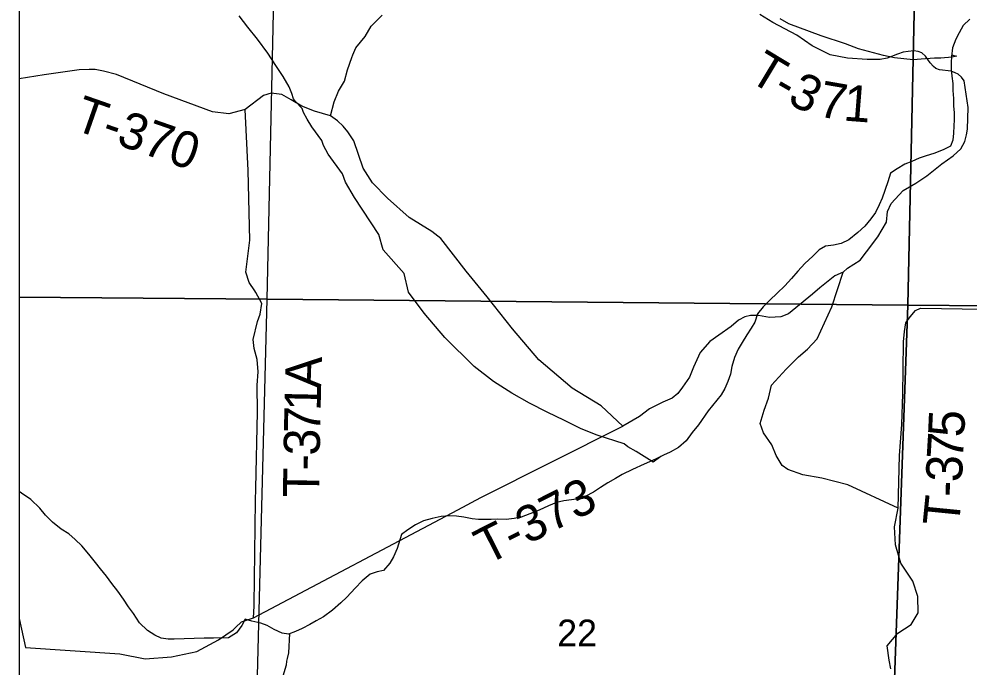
# Model space of a CAD drawing. Extents: x 0 to 34, y 0 to 22.
# Drawn here: x 2.1 to 3.589, y 16.55 to 17.566 of the extents above; entities that cross this region are included whole.
import ezdxf

# ---------------------------------------------------------------- set-up
doc = ezdxf.new("R2010")
doc.units = 0
for name, color, linetype in [('Default', 7, 'Continuous'), ('GM_X_Minor_River', 7, 'Continuous'), ('GM_X_Section', 7, 'Continuous'), ('GM_X_Section_Text', 7, 'Continuous'), ('GM_X_Township_Road', 7, 'Continuous'), ('GM_X_Township_Road_Text', 7, 'Continuous'), ('SH_Cut_Line', 7, 'Continuous'), ('SH_Data', 7, 'Continuous')]:
    doc.layers.add(name, color=color, linetype=linetype)

msp = doc.modelspace()

# ---------------------------------------------------------------- linework, layer by layer
at = {"layer": 'Default'}
for p, q in [((2.1, 19.1502), (2.1, 14.1)), ((2.1, 18.1363), (2.1, 17.1299)), ((2.4891, 17.1265), (2.5107, 18.1291)), ((2.1, 17.1299), (2.4891, 17.1265)), ((2.1, 17.1299), (2.1, 16.1234)), ((2.4891, 17.1265), (2.1, 17.1299)), ((2.4631, 16.1204), (2.4891, 17.1265))]:
    msp.add_line(p, q, dxfattribs=at)
at = {"layer": 'GM_X_Minor_River'}
for p, q in [((2.4586, 17.5536), (2.445, 17.5713)), ((3.3067, 17.5584), (3.293, 17.5666)), ((3.5906, 17.5658), (3.5799, 17.5559)), ((2.474, 17.5344), (2.4586, 17.5536)), ((3.339, 17.5464), (3.3067, 17.5584)), ((3.3573, 17.5395), (3.339, 17.5464)), ((3.5738, 17.5443), (3.5688, 17.5343)), ((3.5799, 17.5559), (3.5738, 17.5443)), ((2.4899, 17.5123), (2.474, 17.5344)), ((3.3957, 17.5272), (3.3573, 17.5395)), ((3.5688, 17.5343), (3.5635, 17.5211)), ((3.4159, 17.5195), (3.3957, 17.5272)), ((3.455, 17.5091), (3.4159, 17.5195)), ((3.5635, 17.5211), (3.5616, 17.5074)), ((2.5027, 17.4931), (2.4899, 17.5123)), ((3.4724, 17.5052), (3.455, 17.5091)), ((3.5016, 17.5019), (3.4724, 17.5052)), ((3.5144, 17.5029), (3.5016, 17.5019)), ((3.5352, 17.5047), (3.5144, 17.5029)), ((3.545, 17.5049), (3.5352, 17.5047)), ((3.5628, 17.5063), (3.545, 17.5049)), ((3.5616, 17.5074), (3.5612, 17.4979)), ((3.562, 17.51), (3.5699, 17.5076)), ((3.5699, 17.5076), (3.5628, 17.5063)), ((2.5143, 17.4761), (2.5027, 17.4931)), ((3.5612, 17.4979), (3.5615, 17.4872)), ((3.5615, 17.4872), (3.5626, 17.4766)), ((2.5233, 17.4599), (2.5143, 17.4761)), ((3.5626, 17.4766), (3.5637, 17.4652)), ((2.5276, 17.4493), (2.5233, 17.4599)), ((3.5637, 17.4652), (3.564, 17.4538)), ((2.5304, 17.441), (2.5276, 17.4493)), ((2.5335, 17.4369), (2.5304, 17.441)), ((3.564, 17.4538), (3.5648, 17.4416)), ((3.5648, 17.4416), (3.5651, 17.4302)), ((2.5439, 17.4256), (2.5335, 17.4369)), ((2.5459, 17.4196), (2.5439, 17.4256)), ((3.5651, 17.4302), (3.5659, 17.4192)), ((2.5518, 17.409), (2.5459, 17.4196)), ((3.5659, 17.4192), (3.5662, 17.4082)), ((2.5592, 17.3969), (2.5518, 17.409)), ((2.5746, 17.3755), (2.5592, 17.3969)), ((3.5657, 17.3986), (3.5649, 17.3872)), ((3.5662, 17.4082), (3.5657, 17.3986)), ((3.5649, 17.3872), (3.5641, 17.3761)), ((2.5771, 17.3675), (2.5746, 17.3755)), ((2.5848, 17.354), (2.5771, 17.3675)), ((3.5603, 17.3665), (3.5486, 17.3608)), ((3.5641, 17.3761), (3.5603, 17.3665)), ((2.6069, 17.3235), (2.5848, 17.354)), ((3.5223, 17.3516), (3.511, 17.3478)), ((3.5344, 17.3554), (3.5223, 17.3516)), ((3.5486, 17.3608), (3.5344, 17.3554)), ((3.4889, 17.3384), (3.4766, 17.3311)), ((3.4998, 17.3425), (3.4889, 17.3384)), ((3.511, 17.3478), (3.4998, 17.3425)), ((2.6117, 17.3103), (2.6069, 17.3235)), ((3.4661, 17.3243), (3.462, 17.3109)), ((3.4766, 17.3311), (3.4661, 17.3243)), ((2.6257, 17.2861), (2.6117, 17.3103)), ((3.462, 17.3109), (3.4529, 17.2851)), ((2.6641, 17.2282), (2.6257, 17.2861)), ((3.4529, 17.2851), (3.4486, 17.2747)), ((3.4426, 17.2627), (3.4356, 17.2526)), ((3.4486, 17.2747), (3.4426, 17.2627)), ((3.4356, 17.2526), (3.4261, 17.2412)), ((3.415, 17.231), (3.4009, 17.2199)), ((3.4261, 17.2412), (3.415, 17.231)), ((2.6709, 17.2043), (2.6641, 17.2282)), ((3.4009, 17.2199), (3.3889, 17.2142)), ((2.7037, 17.1668), (2.6709, 17.2043)), ((3.3546, 17.204), (3.3443, 17.1941)), ((3.3643, 17.2096), (3.3546, 17.204)), ((3.3768, 17.2115), (3.3643, 17.2096)), ((3.3889, 17.2142), (3.3768, 17.2115)), ((3.3443, 17.1941), (3.3317, 17.1827)), ((3.3317, 17.1827), (3.3211, 17.1706)), ((2.7106, 17.1376), (2.7037, 17.1668)), ((3.3112, 17.1592), (3.3005, 17.1474)), ((3.3211, 17.1706), (3.3112, 17.1592)), ((3.3005, 17.1474), (3.2887, 17.136)), ((2.735, 17.1049), (2.7106, 17.1376)), ((3.2887, 17.136), (3.2768, 17.125)), ((3.2665, 17.1144), (3.2577, 17.1035)), ((3.2768, 17.125), (3.2665, 17.1144)), ((2.7678, 17.0666), (2.735, 17.1049)), ((3.2577, 17.1035), (3.2536, 17.0908)), ((3.2536, 17.0908), (3.2478, 17.0811)), ((3.2409, 17.0706), (3.2336, 17.0589)), ((3.2478, 17.0811), (3.2409, 17.0706)), ((2.8136, 17.0209), (2.7678, 17.0666)), ((3.2336, 17.0589), (3.2275, 17.0481)), ((3.2275, 17.0481), (3.2214, 17.0353)), ((3.2214, 17.0353), (3.2177, 17.0211)), ((2.8438, 16.9975), (2.8136, 17.0209)), ((3.2154, 17.0092), (3.2112, 16.9977)), ((3.2177, 17.0211), (3.2154, 17.0092)), ((2.8725, 16.9793), (2.8438, 16.9975)), ((3.2112, 16.9977), (3.2066, 16.9865)), ((2.9004, 16.9634), (2.8725, 16.9793)), ((3.2066, 16.9865), (3.2008, 16.9764)), ((2.9278, 16.9494), (2.9004, 16.9634)), ((3.2008, 16.9764), (3.1803, 16.9514)), ((2.9553, 16.9361), (2.9278, 16.9494)), ((3.1803, 16.9514), (3.165, 16.9296)), ((2.9812, 16.9232), (2.9553, 16.9361)), ((3.0063, 16.9134), (2.9812, 16.9232)), ((3.165, 16.9296), (3.1555, 16.9175)), ((3.0485, 16.9), (3.0063, 16.9134)), ((3.146, 16.9047), (3.1338, 16.894)), ((3.1555, 16.9175), (3.146, 16.9047)), ((3.0543, 16.8951), (3.0485, 16.9)), ((3.0676, 16.8878), (3.0543, 16.8951)), ((3.1338, 16.894), (3.1207, 16.8867)), ((3.0886, 16.8748), (3.0676, 16.8878)), ((3.0978, 16.8757), (3.0802, 16.868)), ((3.0944, 16.8711), (3.0886, 16.8748)), ((3.1062, 16.8798), (3.0944, 16.8711)), ((3.1106, 16.8819), (3.0978, 16.8757)), ((3.1207, 16.8867), (3.1106, 16.8819)), ((3.0615, 16.8594), (3.0457, 16.8516)), ((3.0802, 16.868), (3.0615, 16.8594)), ((3.0353, 16.8452), (3.0229, 16.8387)), ((3.0457, 16.8516), (3.0353, 16.8452)), ((3.0117, 16.8315), (3.0006, 16.824)), ((3.0229, 16.8387), (3.0117, 16.8315)), ((2.1041, 16.8224), (2.1, 16.8249)), ((2.1185, 16.8122), (2.1041, 16.8224)), ((2.9875, 16.8171), (2.9777, 16.8137)), ((3.0006, 16.824), (2.9875, 16.8171)), ((2.1326, 16.799), (2.1185, 16.8122)), ((2.9301, 16.8023), (2.9155, 16.7958)), ((2.9425, 16.8077), (2.9301, 16.8023)), ((2.9542, 16.8103), (2.9425, 16.8077)), ((2.9663, 16.8118), (2.9542, 16.8103)), ((2.9777, 16.8137), (2.9663, 16.8118)), ((2.1413, 16.7878), (2.1326, 16.799)), ((2.1527, 16.7767), (2.1413, 16.7878)), ((2.7618, 16.7856), (2.7475, 16.7825)), ((2.7747, 16.7868), (2.7618, 16.7856)), ((2.7858, 16.7864), (2.7747, 16.7868)), ((2.7972, 16.7848), (2.7858, 16.7864)), ((2.8106, 16.7822), (2.7972, 16.7848)), ((2.887, 16.7846), (2.8764, 16.7824)), ((2.9009, 16.79), (2.887, 16.7846)), ((2.9155, 16.7958), (2.9009, 16.79)), ((2.1663, 16.7658), (2.1527, 16.7767)), ((2.7216, 16.7729), (2.7093, 16.7649)), ((2.7343, 16.7791), (2.7216, 16.7729)), ((2.7475, 16.7825), (2.7343, 16.7791)), ((2.8205, 16.781), (2.8106, 16.7822)), ((2.83, 16.7813), (2.8205, 16.781)), ((2.8403, 16.7812), (2.83, 16.7813)), ((2.8506, 16.7816), (2.8403, 16.7812)), ((2.8639, 16.7812), (2.8506, 16.7816)), ((2.8764, 16.7824), (2.8639, 16.7812)), ((2.1783, 16.7585), (2.1663, 16.7658)), ((2.1881, 16.7497), (2.1783, 16.7585)), ((2.6996, 16.7574), (2.693, 16.7355)), ((2.7093, 16.7649), (2.6996, 16.7574)), ((2.1983, 16.7397), (2.1881, 16.7497)), ((2.2093, 16.7267), (2.1983, 16.7397)), ((2.22, 16.7138), (2.2093, 16.7267)), ((2.693, 16.7355), (2.687, 16.7227)), ((2.2279, 16.7037), (2.22, 16.7138)), ((2.6812, 16.7123), (2.6713, 16.7013)), ((2.687, 16.7227), (2.6812, 16.7123)), ((2.237, 16.6922), (2.2279, 16.7037)), ((2.6506, 16.6953), (2.638, 16.6847)), ((2.6615, 16.6991), (2.6506, 16.6953)), ((2.6713, 16.7013), (2.6615, 16.6991)), ((2.2457, 16.6807), (2.237, 16.6922)), ((2.2548, 16.6684), (2.2457, 16.6807)), ((2.638, 16.6847), (2.6269, 16.6736)), ((2.2636, 16.6561), (2.2548, 16.6684)), ((2.6269, 16.6736), (2.614, 16.6592)), ((2.2715, 16.6442), (2.2636, 16.6561)), ((2.6044, 16.6505), (2.5915, 16.6386)), ((2.614, 16.6592), (2.6044, 16.6505)), ((2.2795, 16.6334), (2.2715, 16.6442)), ((2.5915, 16.6386), (2.5773, 16.6283)), ((2.2891, 16.6188), (2.2795, 16.6334)), ((2.4543, 16.6248), (2.4492, 16.6148)), ((2.465, 16.6217), (2.4543, 16.6248)), ((2.4792, 16.6184), (2.465, 16.6217)), ((2.5661, 16.6219), (2.556, 16.6166)), ((2.5773, 16.6283), (2.5661, 16.6219)), ((2.3012, 16.6067), (2.2891, 16.6188)), ((2.3128, 16.5994), (2.3012, 16.6067)), ((2.4492, 16.6148), (2.4409, 16.6031)), ((2.4888, 16.6149), (2.4792, 16.6184)), ((2.5, 16.6084), (2.4888, 16.6149)), ((2.5123, 16.603), (2.5, 16.6084)), ((2.5332, 16.6056), (2.5223, 16.6014)), ((2.5441, 16.6101), (2.5332, 16.6056)), ((2.556, 16.6166), (2.5441, 16.6101)), ((2.3229, 16.5948), (2.3128, 16.5994)), ((2.3339, 16.5936), (2.3229, 16.5948)), ((2.3434, 16.5935), (2.3339, 16.5936)), ((2.3902, 16.595), (2.3434, 16.5935)), ((2.405, 16.5947), (2.3902, 16.595)), ((2.4282, 16.5954), (2.405, 16.5947)), ((2.4409, 16.6031), (2.4282, 16.5954)), ((2.5223, 16.6014), (2.5123, 16.603)), ((2.5239, 16.6021), (2.5223, 16.572)), ((2.5202, 16.5628), (2.5191, 16.5586)), ((2.5223, 16.572), (2.5202, 16.5628)), ((2.5188, 16.5525), (2.5134, 16.5353)), ((2.5191, 16.5586), (2.5188, 16.5525))]:
    msp.add_line(p, q, dxfattribs=at)
at = {"layer": 'GM_X_Section'}
for p, q in [((2.4891, 17.1265), (2.5107, 18.1291)), ((3.5154, 18.1224), (3.4934, 17.1171)), ((3.4934, 17.1171), (3.5154, 18.1224)), ((2.4631, 16.1204), (2.4891, 17.1265)), ((3.4934, 17.1171), (2.4891, 17.1265)), ((2.4891, 17.1265), (3.4934, 17.1171)), ((3.4934, 17.1171), (3.4577, 16.1051)), ((3.4577, 16.1051), (3.4934, 17.1171)), ((4.4928, 17.1099), (3.4934, 17.1171)), ((3.4934, 17.1171), (4.4928, 17.1099))]:
    msp.add_line(p, q, dxfattribs=at)
at = {"layer": 'GM_X_Township_Road'}
for p, q in [((2.6521, 17.5547), (2.6693, 17.5724)), ((3.2818, 17.5607), (3.2613, 17.5733)), ((3.3192, 17.5406), (3.2818, 17.5607)), ((2.6426, 17.5387), (2.6521, 17.5547)), ((2.6278, 17.521), (2.6426, 17.5387)), ((3.3432, 17.5241), (3.3192, 17.5406)), ((2.6233, 17.5099), (2.6278, 17.521)), ((3.3715, 17.5102), (3.3432, 17.5241)), ((3.4861, 17.5139), (3.4771, 17.5108)), ((3.494, 17.5153), (3.4861, 17.5139)), ((3.5026, 17.5161), (3.494, 17.5153)), ((3.5097, 17.5154), (3.5026, 17.5161)), ((3.5153, 17.5131), (3.5097, 17.5154)), ((2.615, 17.4862), (2.6217, 17.5059)), ((2.6217, 17.5059), (2.6233, 17.5099)), ((3.3989, 17.5049), (3.3715, 17.5102)), ((3.4297, 17.5025), (3.3989, 17.5049)), ((3.4498, 17.5025), (3.4297, 17.5025)), ((3.461, 17.5045), (3.4498, 17.5025)), ((3.4771, 17.5108), (3.461, 17.5045)), ((3.5213, 17.5079), (3.5153, 17.5131)), ((3.5282, 17.4974), (3.5213, 17.5079)), ((2.1944, 17.4865), (2.1394, 17.4785)), ((2.2101, 17.487), (2.1944, 17.4865)), ((2.2193, 17.4867), (2.2101, 17.487)), ((2.2326, 17.4843), (2.2193, 17.4867)), ((2.2526, 17.479), (2.2326, 17.4843)), ((2.6105, 17.4685), (2.615, 17.4862)), ((3.5335, 17.4919), (3.5282, 17.4974)), ((3.5374, 17.4887), (3.5335, 17.4919)), ((3.5432, 17.4866), (3.5374, 17.4887)), ((3.5614, 17.4844), (3.5432, 17.4866)), ((3.5678, 17.4819), (3.5614, 17.4844)), ((2.1394, 17.4785), (2.1, 17.4724)), ((2.3273, 17.4489), (2.2526, 17.479)), ((3.5725, 17.4795), (3.5678, 17.4819)), ((3.5774, 17.4749), (3.5725, 17.4795)), ((3.5816, 17.4694), (3.5774, 17.4749)), ((3.5879, 17.4274), (3.5816, 17.4694)), ((2.6009, 17.4529), (2.6105, 17.4685)), ((2.4031, 17.4204), (2.3273, 17.4489)), ((2.4835, 17.4462), (2.4545, 17.4244)), ((2.4951, 17.4499), (2.4835, 17.4462)), ((2.5118, 17.4479), (2.4951, 17.4499)), ((2.5265, 17.4395), (2.5118, 17.4479)), ((2.5434, 17.4293), (2.5265, 17.4395)), ((2.5941, 17.4362), (2.6009, 17.4529)), ((2.5635, 17.4218), (2.5434, 17.4293)), ((2.5883, 17.4145), (2.5941, 17.4362)), ((3.5867, 17.3933), (3.5879, 17.4274)), ((2.4289, 17.4175), (2.4031, 17.4204)), ((2.4545, 17.4244), (2.4289, 17.4175)), ((2.4591, 17.3283), (2.4545, 17.4244)), ((2.5883, 17.4145), (2.5635, 17.4218)), ((2.5993, 17.4066), (2.5883, 17.4145)), ((2.6084, 17.3978), (2.5993, 17.4066)), ((2.6154, 17.3892), (2.6084, 17.3978)), ((2.6248, 17.3751), (2.6154, 17.3892)), ((3.5829, 17.3741), (3.5853, 17.3844)), ((3.5853, 17.3844), (3.5867, 17.3933)), ((2.6397, 17.3322), (2.6248, 17.3751)), ((3.5766, 17.3623), (3.5829, 17.3741)), ((3.5466, 17.3389), (3.5647, 17.3517)), ((3.5647, 17.3517), (3.5766, 17.3623)), ((3.5231, 17.32), (3.5466, 17.3389)), ((2.4617, 17.2192), (2.4591, 17.3283)), ((2.654, 17.3092), (2.6397, 17.3322)), ((2.6776, 17.2851), (2.654, 17.3092)), ((3.4859, 17.2969), (3.5061, 17.3084)), ((3.5061, 17.3084), (3.5231, 17.32)), ((3.4675, 17.2768), (3.4859, 17.2969)), ((2.7116, 17.2547), (2.6776, 17.2851)), ((3.4617, 17.2644), (3.4675, 17.2768)), ((3.4598, 17.2472), (3.4617, 17.2644)), ((2.7471, 17.2326), (2.7116, 17.2547)), ((3.4464, 17.2246), (3.4598, 17.2472)), ((2.7611, 17.2218), (2.7471, 17.2326)), ((2.4556, 17.1692), (2.4617, 17.2192)), ((2.8011, 17.1708), (2.7611, 17.2218)), ((3.4285, 17.201), (3.4464, 17.2246)), ((3.3986, 17.1753), (3.4185, 17.1876)), ((3.4185, 17.1876), (3.4285, 17.201)), ((3.3919, 17.1689), (3.3986, 17.1753)), ((2.4609, 17.1527), (2.4556, 17.1692)), ((2.8338, 17.1301), (2.8011, 17.1708)), ((3.3787, 17.1631), (3.3553, 17.1442)), ((3.3742, 17.1145), (3.3919, 17.1689)), ((3.3919, 17.1689), (3.3787, 17.1631)), ((2.4698, 17.1395), (2.4609, 17.1527)), ((3.3553, 17.1442), (3.3439, 17.1343)), ((2.4711, 17.1371), (2.4698, 17.1395)), ((2.4805, 17.1198), (2.4711, 17.1371)), ((2.8737, 17.0804), (2.8338, 17.1301)), ((3.3439, 17.1343), (3.3179, 17.1129)), ((2.4782, 17.1033), (2.4805, 17.1198)), ((3.3179, 17.1129), (3.3063, 17.1036)), ((3.3511, 17.0644), (3.3742, 17.1145)), ((3.5054, 17.1087), (3.5133, 17.1127)), ((3.5133, 17.1127), (3.6117, 17.111)), ((2.4738, 17.0917), (2.4782, 17.1033)), ((3.238, 17.099), (3.2279, 17.0937)), ((3.2465, 17.1013), (3.238, 17.099)), ((3.2592, 17.1013), (3.2465, 17.1013)), ((3.2764, 17.0981), (3.2592, 17.1013)), ((3.2943, 17.0988), (3.2764, 17.0981)), ((3.3063, 17.1036), (3.2943, 17.0988)), ((3.4905, 17.0895), (3.4968, 17.0992)), ((3.4968, 17.0992), (3.5054, 17.1087)), ((2.4671, 17.0633), (2.4738, 17.0917)), ((3.2165, 17.0837), (3.197, 17.0702)), ((3.2279, 17.0937), (3.2165, 17.0837)), ((3.488, 17.0758), (3.4905, 17.0895)), ((2.915, 17.0316), (2.8737, 17.0804)), ((3.197, 17.0702), (3.1831, 17.0605)), ((3.4867, 17.0596), (3.488, 17.0758)), ((2.4684, 17.0493), (2.4671, 17.0633)), ((3.1831, 17.0605), (3.1679, 17.0431)), ((3.3361, 17.0482), (3.3511, 17.0644)), ((3.4861, 17.0159), (3.4867, 17.0596)), ((2.4734, 17.032), (2.4684, 17.0493)), ((3.1679, 17.0431), (3.1576, 17.0199)), ((3.3219, 17.0362), (3.3361, 17.0482)), ((2.475, 17.0127), (2.4734, 17.032)), ((2.9674, 16.9872), (2.915, 17.0316)), ((3.3027, 17.0167), (3.3219, 17.0362)), ((2.4736, 16.9917), (2.475, 17.0127)), ((3.1576, 17.0199), (3.1509, 17.0045)), ((3.2796, 16.9917), (3.3027, 17.0167)), ((3.4855, 16.9781), (3.4861, 17.0159)), ((3.1509, 17.0045), (3.1401, 16.9887)), ((2.4739, 16.9495), (2.4736, 16.9917)), ((3.0126, 16.9593), (2.9674, 16.9872)), ((3.1328, 16.9785), (3.1241, 16.9715)), ((3.1401, 16.9887), (3.1328, 16.9785)), ((3.2752, 16.9712), (3.2796, 16.9917)), ((3.4841, 16.9301), (3.4855, 16.9781)), ((3.1094, 16.9649), (3.0883, 16.9548)), ((3.1241, 16.9715), (3.1094, 16.9649)), ((3.2681, 16.9524), (3.2752, 16.9712)), ((2.4712, 16.8304), (2.4739, 16.9495)), ((3.0465, 16.9274), (3.0126, 16.9593)), ((3.0883, 16.9548), (3.0725, 16.9426)), ((3.262, 16.9316), (3.2681, 16.9524)), ((3.0725, 16.9426), (3.0465, 16.9274)), ((2.8242, 16.8156), (3.0465, 16.9274)), ((3.2673, 16.9171), (3.262, 16.9316)), ((3.4805, 16.8814), (3.4841, 16.9301)), ((3.2802, 16.8984), (3.2673, 16.9171)), ((3.287, 16.8814), (3.2802, 16.8984)), ((3.2966, 16.8659), (3.287, 16.8814)), ((3.478, 16.799), (3.4805, 16.8814)), ((3.3053, 16.8593), (3.2966, 16.8659)), ((3.3287, 16.8512), (3.3053, 16.8593)), ((3.3584, 16.846), (3.3287, 16.8512)), ((3.3995, 16.8354), (3.3584, 16.846)), ((2.4709, 16.8102), (2.4712, 16.8304)), ((3.478, 16.799), (3.3995, 16.8354)), ((2.7877, 16.7963), (2.8242, 16.8156)), ((2.4687, 16.647), (2.4709, 16.8102)), ((2.4675, 16.627), (2.7877, 16.7963)), ((3.4723, 16.7698), (3.478, 16.799)), ((3.4739, 16.7415), (3.4723, 16.7698)), ((3.4824, 16.7127), (3.4739, 16.7415)), ((3.5011, 16.6844), (3.4824, 16.7127)), ((3.5091, 16.6603), (3.5011, 16.6844)), ((3.5097, 16.6347), (3.5091, 16.6603)), ((2.4675, 16.627), (2.4685, 16.6452)), ((2.4685, 16.6452), (2.4687, 16.647)), ((2.1, 16.6259), (2.1102, 16.5805)), ((2.4395, 16.6115), (2.4487, 16.6205)), ((2.4487, 16.6205), (2.4675, 16.627)), ((3.4984, 16.6165), (3.5097, 16.6347)), ((2.413, 16.5924), (2.4356, 16.6081)), ((2.4356, 16.6081), (2.4372, 16.6093)), ((2.4372, 16.6093), (2.4395, 16.6115)), ((3.4778, 16.6029), (3.4984, 16.6165)), ((2.3789, 16.5742), (2.413, 16.5924)), ((3.4609, 16.583), (3.4778, 16.6029)), ((2.1102, 16.5805), (2.2583, 16.5702)), ((3.4643, 16.5605), (3.4609, 16.583)), ((2.2583, 16.5702), (2.2978, 16.5627)), ((2.2978, 16.5627), (2.339, 16.5658)), ((2.339, 16.5658), (2.3789, 16.5742)), ((3.4665, 16.5468), (3.4643, 16.5605))]:
    msp.add_line(p, q, dxfattribs=at)
at = {"layer": 'SH_Cut_Line'}
msp.add_line((2.1, 20.9), (2.1, 14.1), dxfattribs=at)
at = {"layer": 'SH_Data'}
msp.add_line((2.1, 20.9), (2.1, 14.1), dxfattribs=at)

# ---------------------------------------------------------------- texts
at = {"layer": 'GM_X_Section_Text'}
msp.add_text('22', height=0.04186, rotation=0, dxfattribs=at).set_placement((2.9438, 16.5822))
at = {"layer": 'GM_X_Township_Road_Text'}
for s, height, rotation, p in [('T', 0.0568, 328.8782, (3.2414, 17.4708)), ('3', 0.0568, 333.8375, (3.3027, 17.4346)), ('-', 0.0568, 330.0266, (3.2789, 17.4482)), ('7', 0.0568, 350.1359, (3.3509, 17.4138)), ('1', 0.0568, 355.5926, (3.3912, 17.407)), ('T-370', 0.05682, 340.7819, (2.1831, 17.3935)), ('A', 0.0568, 88.007, (2.5735, 16.9857)), ('1', 0.0568, 88.7978, (2.5728, 16.9509)), ('7', 0.0568, 88.9591, (2.5721, 16.916)), ('5', 0.0568, 87.2987, (3.5816, 16.9094)), ('3', 0.0568, 89.0164, (2.5715, 16.881)), ('7', 0.0568, 86.5373, (3.5795, 16.8737)), ('-', 0.0568, 89.0326, (2.5712, 16.8577)), ('3', 0.0568, 87.9752, (3.5783, 16.8391)), ('T', 0.0568, 89.0228, (2.5704, 16.8152)), ('T-373', 0.05682, 26.9405, (2.8333, 16.709)), ('-', 0.0568, 88.4418, (3.5776, 16.8159)), ('T', 0.0568, 84.3295, (3.5732, 16.7691))]:
    msp.add_text(s, height=height, rotation=rotation, dxfattribs=at).set_placement(p)

doc.saveas('drawing.dxf')
